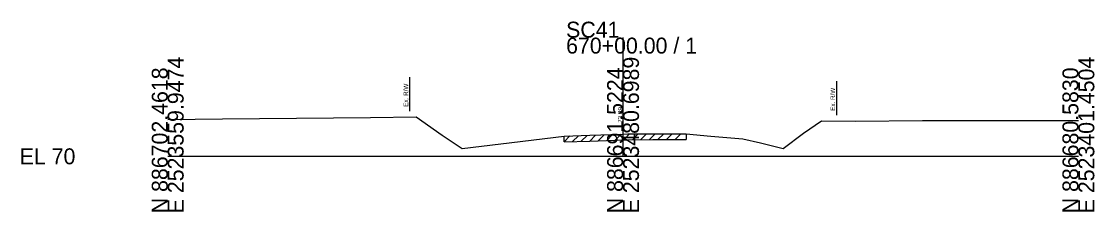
# Model space of a CAD drawing. Extents: x -26 to 183, y -10 to 24021.
# Drawn here: x -25.7 to 162.8, y 2490.3 to 2523.7 of the extents above; entities that cross this region are included whole.
import ezdxf

# ---------------------------------------------------------------- set-up
doc = ezdxf.new("R2010")
doc.units = 0
for name, color, linetype in [('RD_GPK_XS_Cell', 7, 'Continuous'), ('RD_XS_ExGround', 7, 'Continuous'), ('RD_XS_ExPaveRet', 7, 'Continuous'), ('RD_XS_ExRW', 7, 'Continuous'), ('RD_XS_TX_Elev_EX', 7, 'Continuous')]:
    doc.layers.add(name, color=color, linetype=linetype)

msp = doc.modelspace()

# ---------------------------------------------------------------- linework, layer by layer
at = {"layer": 'RD_GPK_XS_Cell'}
for p, q in [((80, 2500), (80, 2520.84)), ((0, 2500), (80, 2500)), ((80, 2500), (160, 2500))]:
    msp.add_line(p, q, dxfattribs=at)
at = {"layer": 'RD_XS_ExGround'}
for p, q in [((0, 2506.48), (9.63, 2506.56)), ((9.63, 2506.56), (35.63, 2506.79)), ((35.63, 2506.79), (43.63, 2506.95)), ((43.63, 2506.95), (48.25, 2503.72)), ((111.7, 2504.07), (114.89, 2506.25)), ((114.89, 2506.25), (120.87, 2506.15)), ((120.87, 2506.15), (132.64, 2506.27)), ((132.64, 2506.27), (160, 2506.3)), ((48.25, 2503.72), (51.74, 2501.35)), ((74.16, 2503.69), (80, 2503.89)), ((80, 2503.89), (80.85, 2503.92)), ((80.85, 2503.92), (85.23, 2503.93)), ((85.23, 2503.93), (91.09, 2503.94)), ((91.09, 2503.94), (95.45, 2503.56)), ((108.15, 2501.39), (111.7, 2504.07)), ((51.74, 2501.35), (58.54, 2502.18)), ((58.54, 2502.18), (69.64, 2503.54)), ((69.64, 2503.54), (74.16, 2503.69)), ((95.45, 2503.56), (101.04, 2503.09)), ((101.04, 2503.09), (104.15, 2502.34)), ((104.15, 2502.34), (108.15, 2501.39))]:
    msp.add_line(p, q, dxfattribs=at)
at = {"layer": 'RD_XS_ExPaveRet'}
for p, q in [((74.14, 2502.68), (75.17, 2503.72)), ((75.64, 2502.74), (76.67, 2503.77)), ((77.14, 2502.79), (78.17, 2503.83)), ((78.64, 2502.84), (79.67, 2503.88)), ((80.14, 2502.9), (81.16, 2503.92)), ((81.64, 2502.92), (82.64, 2503.93)), ((83.14, 2502.93), (84.14, 2503.93)), ((84.64, 2502.93), (85.64, 2503.93)), ((86.14, 2502.93), (87.14, 2503.93)), ((87.64, 2502.93), (88.64, 2503.94)), ((89.14, 2502.94), (90.14, 2503.94)), ((91.09, 2503.94), (91.09, 2502.94)), ((69.64, 2502.54), (70.67, 2503.58)), ((69.64, 2502.54), (69.64, 2503.54)), ((69.64, 2502.54), (74.16, 2502.69)), ((71.14, 2502.59), (72.17, 2503.62)), ((72.64, 2502.64), (73.67, 2503.67)), ((74.16, 2502.69), (80, 2502.89)), ((80, 2502.89), (80.85, 2502.92)), ((80.85, 2502.92), (85.23, 2502.93)), ((85.23, 2502.93), (91.09, 2502.94))]:
    msp.add_line(p, q, dxfattribs=at)
at = {"layer": 'RD_XS_ExRW'}
for p, q in [((42.5, 2513.92), (42.5, 2507.92)), ((117.5, 2513.21), (117.5, 2507.21))]:
    msp.add_line(p, q, dxfattribs=at)

# ---------------------------------------------------------------- texts
at = {"layer": 'RD_GPK_XS_Cell'}
for s, p in [('SC41', (70, 2520.84)), ('670+00.00 / 1', (70, 2518.04)), ('EL 70', (-26, 2498.6))]:
    msp.add_text(s, height=2.8, dxfattribs=at).set_placement(p)
for s, p in [('E 2523559.9474', (2.8, 2490)), ('E 2523480.6989', (82.8, 2490)), ('E 2523401.4504', (162.8, 2490)), ('N 886702.4618', (0, 2490)), ('N 886691.5224', (80, 2490)), ('N 886680.5830', (160, 2490))]:
    msp.add_text(s, height=2.8, rotation=90, dxfattribs=at).set_placement(p)
at = {"layer": 'RD_XS_ExRW'}
for p in [(42.25, 2508.71), (117.25, 2507.99)]:
    msp.add_text('Ex. R/W ', height=0.8, rotation=90, dxfattribs=at).set_placement(p)
at = {"layer": 'RD_XS_TX_Elev_EX'}
msp.add_text('73.89', height=0.8, rotation=90, dxfattribs=at).set_placement((79.9, 2505.89))

doc.saveas('drawing.dxf')
